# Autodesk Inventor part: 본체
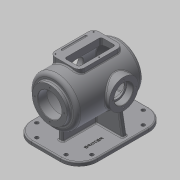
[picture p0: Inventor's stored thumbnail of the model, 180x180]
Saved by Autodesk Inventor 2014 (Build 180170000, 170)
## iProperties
Created: 2016-02
Part Number: 본체
Material: Aluminum 6061
Document SubType Name: Modeling
Designer: mduedu
Density: 2.71 g/cm^3
Appearance: Aluminum - Flat
Mass: 4129.73 g
Surface Area: 2907.55 cm^2
Volume: 1523.88 cm^3
Author: mduedu
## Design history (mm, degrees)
sketch "스케치2"
  geometry: L1 (0, 100)-(0, -100); L2 (65, -75.993)-(65, 100); L3 (65, 100)-(0, 100); A1 r 100 centre (0, 0) between (0, -100) and (65, -75.993); 2 further points
  constraints: 6 end point, 2 midpoint, 2 point on circle, 1 centre point, 1 coincident, 1 horizontal, 1 parallel, 1 vertical
  dimensions: "d3" = 200 distance of L1.start L1.end; "d5" = 130 diameter of L2 L1; "d6" = 100 radius of A1
revolve "회전1" sketch "스케치2" stored, may be unused: angle "d7" = 90 deg
sketch "스케치3"
  geometry: C1 r 47.5 at (0, 0); 1 further point
  constraints: 1 centre point, 1 coincident
  dimensions: "d8" = 95 diameter of C1
extrude "돌출2" join sketch "스케치3" distance "d10" = 10; taper "d11" = 0 deg
sketch "스케치5"
  geometry: L1 (47.5, 110)-(47.5, 100) reference; L2 (47.5, 100)-(65, 100) reference; L3 (65, 100)-(65, -75.993) reference; L4 (-65, -75.993)-(-65, 100) reference; L5 (-65, 100)-(-47.5, 100) reference; L6 (-47.5, 100)-(-47.5, 110) reference; L7 (-47.5, 110)-(47.5, 110) reference; L8 (55, 85)-(55, -71.239); L9 (0, 85)-(55, 85); L10 (0, 85)-(0, -90); A1 r 100 centre (0, 0) between (0, -100) and (65, -75.993) reference; A2 r 100 centre (0, 0) between (-65, -75.993) and (0, -100) reference; A3 r 90 centre (0, 0) between (0, -90) and (55, -71.239); 1 further point
  constraints: 6 end point, 2 point on circle, 1 centre point, 1 parallel, 1 perpendicular, 1 point on line, 1 vertical
  dimensions: "d13" = 10 distance between parallel lines of L3 L8; "d14" = 10 radial gap between concentric circles of A3 A1; "d15" = 15 distance between parallel lines of L9 L2
revolve "회전2" sketch "스케치5" stored, may be unused: angle "d16" = 90 deg
hole "구멍1" diameter "d19" = 65; stored, may be unused: countersink angle "d23" = 90 deg, drill point angle "d25" = 118 deg; dims "d17" = 10, "d18" = 10, "d20" = 6, "d21" = 4, "d22" = 2, "d24" = 8
node "작업 평면1"
sketch "스케치6"
  geometry: L1 (47.5, 110)-(-47.5, 110) reference; C1 r 40 at (0, -17); 1 further point
  constraints: 1 centre point, 1 vertical alignment
  dimensions: "d27" = 80 diameter of C1; "d29" = 127 distance from line of C1.centre L1
extrude "돌출3" join sketch "스케치6" stored distance "d30" = 10; taper "d31" = 0 deg
hole "구멍2" diameter "d34" = 42; stored, may be unused: countersink angle "d38" = 90 deg, drill point angle "d40" = 118 deg; dims "d32" = 10, "d33" = 10, "d35" = 6, "d36" = 52, "d37" = 18, "d39" = 8
sketch "스케치7" dims "d41" = 65
  geometry: C1 r 40 at (0, 0) reference; 3 further points
  constraints: 2 vertical alignment, 1 coincident, 2 other
hole "구멍3" sketch "스케치7" at (0, 32.5) diameter "d43" = 3.242; stored, may be unused: countersink angle "d47" = 90 deg, drill point angle "d49" = 118 deg; dims "d44" = 11, "d45" = 13, "d46" = 18, "d48" = 13
sketch "스케치8" dims "d53" = 80
  geometry: 3 further points
  constraints: 2 vertical alignment, 1 coincident, 2 other
hole "구멍4" sketch "스케치8" at (0, 40) diameter "d56" = 3.242; stored, may be unused: countersink angle "d60" = 90 deg, drill point angle "d62" = 118 deg; dims "d57" = 11, "d58" = 13, "d59" = 18, "d61" = 13
fillet "모깎기1" dims "d66" = 10
fillet "모깎기2" dims "d67" = 3
fillet "모깎기3" dims "d68" = 0.3
chamfer "모따기1" distance "d69" = 1; stored, may be unused: second distance "d70" = 2, angle "d71" = 45 deg
node "작업 평면5"
sketch "스케치23"
  geometry: L1 (6, 80)-(-6, 80); L2 (-6, 80)-(-6, -60); L3 (-6, -60)-(6, -60); L4 (6, -60)-(6, 80); L5 (-55, 100)-(55, 100) reference; 2 further points
  constraints: 8 end point, 2 parallel, 1 horizontal, 1 midpoint, 1 perpendicular, 1 vertical alignment
  dimensions: "d177" = 12 distance of L1.start L1.end; "d179" = 140 distance of L3.end L1.start; "d180" = 20 distance between parallel lines of L1 L5
extrude "돌출14" join sketch "스케치23" stored distance "d181" = 10; taper "d182" = 0 deg
node "작업 평면6"
sketch "스케치15"
  geometry: L1 (-30, 60)-(50, 60); L2 (50, 60)-(50, -60); L3 (50, -60)-(-30, -60); L4 (-30, -60)-(-30, 60); 3 further points
  constraints: 8 end point, 2 parallel, 1 horizontal, 1 horizontal alignment, 1 midpoint, 1 perpendicular, 1 vertical alignment
  dimensions: "d110" = 80 distance of L2.end L3.end; "d112" = 60 distance from line of L3 point (10, 0); "d113" = 120 distance of L1.end L2.end; "d149" = 30 distance from line of L4 point (0, 0)
extrude "돌출8" join sketch "스케치15" stored distance "d114" = 10; taper "d115" = 0 deg
fillet "모깎기7" dims "d116" = 15
sketch "스케치16"
  geometry: L1 (-30, -45)-(-30, 45) reference; L2 (-15, 60)-(35, 60) reference; L3 (35, -60)-(-15, -60) reference; L4 (-20, -45)-(-20, 45); L5 (-15, 50)-(15, 50); L6 (20, 45)-(20, -45); L7 (15, -50)-(-15, -50); L8 (50, 45)-(50, -45) reference; A1 r 15 centre (-15, -45) between (-30, -45) and (-15, -60) reference; A2 r 15 centre (-15, 45) between (-15, 60) and (-30, 45) reference; A3 r 5 centre (-15, -45) between (-20, -45) and (-15, -50); A4 r 5 centre (-15, 45) between (-15, 50) and (-20, 45); A5 r 5 centre (15, 45) between (20, 45) and (15, 50); A6 r 5 centre (15, -45) between (15, -50) and (20, -45); A7 r 15 centre (35, 45) between (50, 45) and (35, 60) reference; A8 r 15 centre (35, -45) between (35, -60) and (50, -45) reference
  constraints: 8 end point, 8 point on circle, 4 centre point, 2 equal radius, 3 other
  dimensions: "d137" = 10 distance between parallel lines of L4 L1; "d150" = 40 distance between parallel lines of L6 L4; "d151" = 100 distance between parallel lines of L7 L5
extrude "돌출9" cut sketch "스케치16" stored distance "d118" = 10; taper "d119" = 0 deg
fillet "모깎기8" dims "d120" = 3
sketch "스케치17"
  geometry: L1 (-30, -45)-(-30, 45) reference; L2 (-20, 45)-(-20, -45) reference; L3 (-15, -50)-(15, -50) reference; L4 (20, -45)-(20, 45) reference; L5 (15, 50)-(-15, 50) reference; L6 (-15, 60)-(35, 60) reference; L7 (35, -60)-(-15, -60) reference; L8 (15, 55)-(-15, 55); L9 (-25, 45)-(-25, -45); L10 (-15, -55)-(15, -55); L11 (25, -45)-(25, 45); L12 (50, 45)-(50, -45) reference; L13 (35, 55)-(-15, 55); L14 (-25, 45)-(-25, -45); L15 (-15, -55)-(35, -55); L16 (45, -45)-(45, 45); A1 r 5 centre (-15, 45) between (-15, 50) and (-20, 45) reference; A2 r 5 centre (-15, -45) between (-20, -45) and (-15, -50) reference; A3 r 5 centre (15, -45) between (15, -50) and (20, -45) reference; A4 r 5 centre (15, 45) between (20, 45) and (15, 50) reference; A5 r 15 centre (-15, 45) between (-15, 60) and (-30, 45) reference; A6 r 15 centre (-15, -45) between (-30, -45) and (-15, -60) reference; A7 r 10 centre (-15, 45) between (-15, 55) and (-25, 45); A8 r 10 centre (-15, -45) between (-25, -45) and (-15, -55); A9 r 10 centre (15, -45) between (15, -55) and (25, -45); A10 r 10 centre (15, 45) between (25, 45) and (15, 55); A11 r 15 centre (35, 45) between (50, 45) and (35, 60) reference; A12 r 15 centre (35, -45) between (35, -60) and (50, -45) reference; A13 r 10 centre (-15, 45) between (-15, 55) and (-25, 45); A14 r 10 centre (-15, -45) between (-25, -45) and (-15, -55); A15 r 10 centre (35, -45) between (35, -55) and (45, -45); A16 r 10 centre (35, 45) between (45, 45) and (35, 55); 6 further points
  constraints: 18 point on circle, 16 end point, 8 centre point, 4 midpoint, 4 tangent, 11 other
  dimensions: "d138" = 5 distance between parallel lines of L8 L6; "d157" = 5 distance between parallel lines of L12 L16
hole "구멍5" sketch "스케치17" at (-25, 0), (42.071, 52.071), (42.071, -52.071) diameter "d122" = 3.242; stored, may be unused: countersink angle "d126" = 90 deg, drill point angle "d128" = 118 deg; dims "d123" = 9, "d124" = 13, "d125" = 18, "d127" = 11
sketch "스케치19"
  geometry: L1 (-50, 70)-(-35, 70) reference; L2 (-50, 42.603)-(-50, 70) reference; C1 r 2.5 at (-43, 70); 1 further point
  constraints: 1 centre point, 1 point on line
  dimensions: "d152" = 5 diameter of C1; "d153" = 7 distance from line of C1.centre L2
extrude "돌출11" cut sketch "스케치19" stored distance "d154" = 70; taper "d155" = 0 deg
fillet "모깎기11" dims "d156" = 2.5
sketch "스케치20"
  geometry: L1 (-90, 120)-(90, 120); L2 (90, 120)-(90, -120); L3 (90, -120)-(-90, -120); L4 (-90, -120)-(-90, 120); 3 further points
  constraints: 8 end point, 2 parallel, 2 vertical alignment, 1 coincident, 1 horizontal, 1 midpoint, 1 perpendicular
  dimensions: "d162" = 180 distance of L1.start L1.end; "d164" = 240 distance of L1.end L2.end; "d165" = 120 distance from line of L1 point (0, 0)
extrude "돌출12" join sketch "스케치20" distance "d166" = 10; taper "d167" = 0 deg
fillet "모깎기12" dims "d168" = 50
node "작업 평면8"
  node "작업축1"
sketch "스케치24"
  geometry: L1 (128, 34.121)-(127.026, 32.5) reference; L2 (127.026, 32.5)-(128, 30.879) reference; L3 (128, 30.879)-(141, 30.879) reference; L4 (141, 30.879)-(141, 27) reference; L5 (141, 27)-(140, 26) reference; L6 (140, 26)-(123.3, 26) reference; L7 (123, 25.7)-(123, 21) reference; L8 (123, 21)-(116.833, 21) reference; L9 (86, 51.235)-(86, 70) reference; L10 (86, 70)-(106.5, 70) reference; L11 (111.5, 70)-(116, 70) reference; L12 (116, 70)-(116, 42.603) reference; L13 (118.678, 40)-(141, 40) reference; L14 (141, 40)-(141, 34.121) reference; L15 (141, 34.121)-(128, 34.121) reference; L16 (4, -34.121)-(4.974, -32.5) reference; L17 (4.974, -32.5)-(4, -30.879) reference; L18 (4, -30.879)-(-9, -30.879) reference; L19 (-9, -30.879)-(-9, -27) reference; L20 (-9, -27)-(-8, -26) reference; L21 (-8, -26)-(8.7, -26) reference; L22 (9, -25.7)-(9, -21) reference; L23 (9, -21)-(15.167, -21) reference; L24 (116.833, -21)-(123, -21) reference; L25 (123, -21)-(123, -25.7) reference; L26 (123.3, -26)-(140, -26) reference; L27 (140, -26)-(141, -27) reference; L28 (141, -27)-(141, -30.879) reference; L29 (141, -30.879)-(128, -30.879) reference; L30 (128, -30.879)-(127.026, -32.5) reference; L31 (127.026, -32.5)-(128, -34.121) reference; L32 (128, -34.121)-(141, -34.121) reference; L33 (141, -34.121)-(141, -40) reference; L34 (141, -40)-(118.678, -40) reference; L35 (72, -64.722)-(72, -100) reference; L36 (72, -100)-(156, -100) reference; L37 (156, -100)-(156, -110) reference; L38 (156, -110)-(-24, -110) reference; L39 (-24, -110)-(-24, -100) reference; L40 (-24, -100)-(60, -100) reference; L41 (60, -100)-(60, -64.722) reference; L42 (13.322, -40)-(-9, -40) reference; L43 (-9, -40)-(-9, -34.121) reference; L44 (-9, -34.121)-(4, -34.121) reference; L45 (4.974, 32.5)-(4, 34.121) reference; L46 (4, 34.121)-(-9, 34.121) reference; L47 (-9, 34.121)-(-9, 40) reference; L48 (-9, 40)-(13.322, 40) reference; L49 (36, 59.456)-(36, 70) reference; L50 (36, 70)-(46, 70) reference; L51 (46, 70)-(46, 51.235) reference; L52 (15.167, 21)-(9, 21) reference; L53 (9, 21)-(9, 25.7) reference; L54 (8.7, 26)-(-8, 26) reference; L55 (-8, 26)-(-9, 27) reference; L56 (-9, 27)-(-9, 30.879) reference; L57 (-9, 30.879)-(4, 30.879) reference; L58 (4, 30.879)-(4.974, 32.5) reference; L59 (-1, -40)-(-11.58, -100); A1 r 0.3 centre (123.3, 25.7) between (123.3, 26) and (123, 25.7) reference; A2 r 55 centre (66, 0) between (116.833, 21) and (86, 51.235) reference; A3 r 2.5 centre (109, 70) between (106.5, 70) and (111.5, 70) reference; A4 r 3 centre (119, 42.603) between (116, 42.603) and (116.516, 40.92) reference; A5 r 0.3 centre (8.7, -25.7) between (8.7, -26) and (9, -25.7) reference; A6 r 55 centre (66, 0) between (15.167, -21) and (116.833, -21) reference; A7 r 0.3 centre (123.3, -25.7) between (123, -25.7) and (123.3, -26) reference; A8 r 65 centre (66, 0) between (72, -64.722) and (116.354, -41.103) reference; A9 r 65 centre (66, 0) between (15.646, -41.103) and (60, -64.722) reference; A10 r 65 centre (66, 0) between (34.456, 56.833) and (15.646, 41.103) reference; A11 r 3 centre (33, 59.456) between (34.456, 56.833) and (36, 59.456) reference; A12 r 55 centre (66, 0) between (46, 51.235) and (15.167, 21) reference; A13 r 0.3 centre (8.7, 25.7) between (9, 25.7) and (8.7, 26) reference; 1 further point
  constraints: 2 end point, 2 point on line, 4 other
  dimensions: "d184" = 8 distance of L59.start L42.end; "d185" = 100 deg angle of L59 L40
feature "리브2" sketch "스케치24" dims "d186" = 1, "d187" = 12, "d188" = 0, "d189" = 0, "d190" = 1, "d191" = 1
fillet "모깎기15" dims "d192" = 3
fillet "모깎기16" dims "d193" = 3
sketch "스케치25"
  geometry: L1 (90, -70)-(90, 70) reference; L2 (40, 120)-(-40, 120) reference; L3 (-90, 70)-(-90, -70) reference; L4 (-40, -120)-(40, -120) reference; L5 (-74.004, 8)-(-9, 8) reference; L6 (-80.097, 20)-(-80.097, 14) reference; L7 (-9, 26)-(-74.004, 26) reference; L8 (-9, 57)-(-9, 26) reference; L9 (3, 63)-(-3, 63) reference; L10 (9, 26)-(9, 57) reference; L11 (74.004, 26)-(9, 26) reference; L12 (80.097, 14)-(80.097, 20) reference; L13 (9, 8)-(74.004, 8) reference; L14 (9, -77)-(9, 8) reference; L15 (-3, -83)-(3, -83) reference; L16 (-9, 8)-(-9, -77) reference; L17 (-40, 105)-(40, 105); L18 (75, 70)-(75, -70); L19 (40, -105)-(-40, -105); L20 (-75, -70)-(-75, 70); C1 r 5 at (-75, 70); C2 r 5 at (-40, 105); C3 r 5 at (40, 105); C4 r 5 at (75, 70); C5 r 5 at (75, -70); C6 r 5 at (40, -105); C7 r 5 at (-40, -105); C8 r 5 at (-75, -70); A1 r 50 centre (40, 70) between (90, 70) and (40, 120) reference; A2 r 50 centre (-40, 70) between (-40, 120) and (-90, 70) reference; A3 r 50 centre (-40, -70) between (-90, -70) and (-40, -120) reference; A4 r 50 centre (40, -70) between (40, -120) and (90, -70) reference; A5 r 6 centre (-3, 57) between (-3, 63) and (-9, 57) reference; A6 r 6 centre (3, 57) between (9, 57) and (3, 63) reference; A7 r 6 centre (3, -77) between (3, -83) and (9, -77) reference; A8 r 6 centre (-3, -77) between (-9, -77) and (-3, -83) reference; A9 r 35 centre (40, 70) between (75, 70) and (40, 105); A10 r 35 centre (40, -70) between (40, -105) and (75, -70); A11 r 35 centre (-40, -70) between (-75, -70) and (-40, -105); A12 r 35 centre (-40, 70) between (-40, 105) and (-75, 70); 5 further points; 4 other entities
  constraints: 12 centre point, 8 coincident, 8 end point, 8 point on circle, 7 equal radius, 11 other
  dimensions: "d194" = 15 distance between parallel lines of L17 L2; "d195" = 10 diameter of C1
extrude "돌출15" cut sketch "스케치25" stored distance "d197" = 10; taper "d198" = 0 deg
fillet "모깎기14" dims "d170" = 3
sketch "스케치22"
  geometry: L1 (90, -70)-(90, 70) reference; 2 further points
  constraints: 1 other
  dimensions: "d174" = 40 distance from line of L1 point (50, -40); "d199" = 40 vertical distance of point (50, -40) point (0, 0)
feature "엠보싱2" sketch "스케치22" dims "d13" = 10, "d175" = 0.5, "d176" = 0
node "솔리드2"
pattern_circular "원형 패턴1" dims angle "d51" = 360 deg
mirror "대칭1"
pattern_circular "원형 패턴2" dims angle "d64" = 360 deg
mirror "대칭3"
node "투영된 루프2"
node "절단 모서리 투영1"
node "절단 모서리 투영2"
node "절단 모서리 투영3"
node "절단 모서리 투영4"
other parameters: "d26" = 75, "d183" = 0
